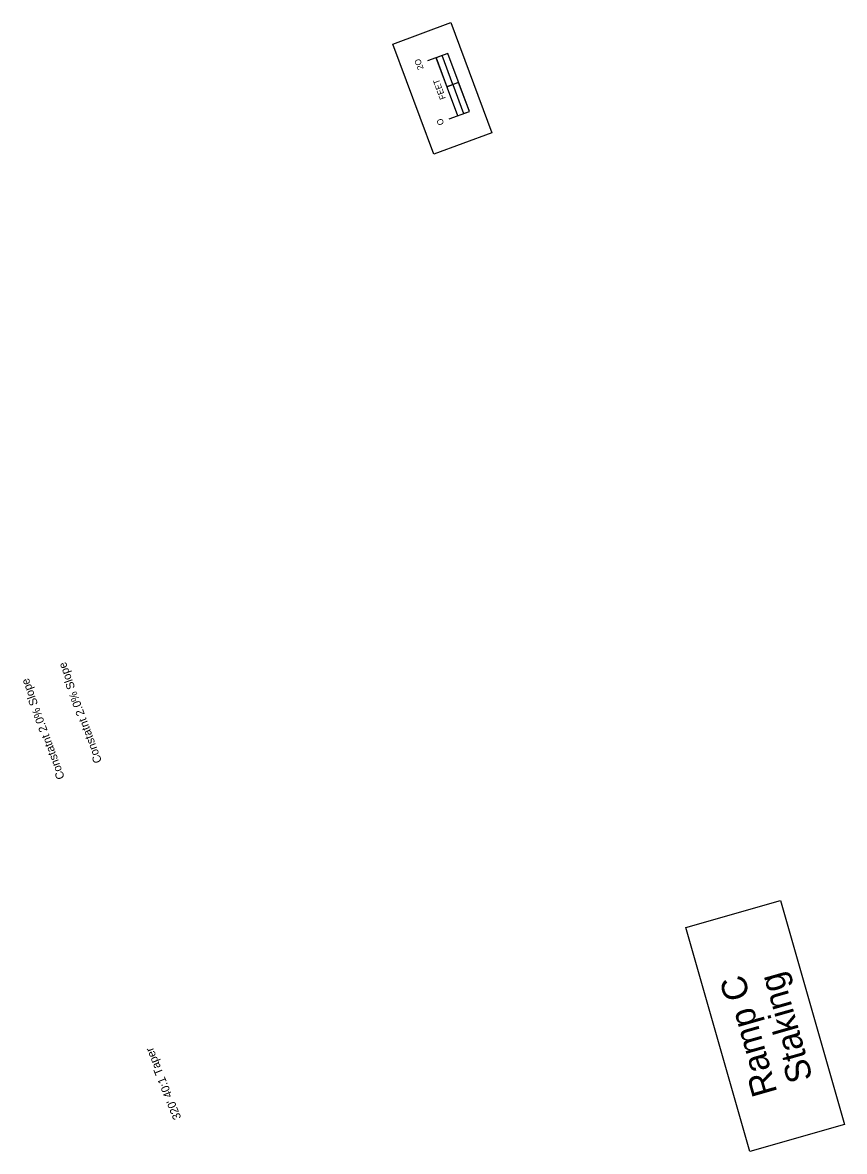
# Model space of a CAD drawing. Extents: x 20506035 to 20507470, y 7969245 to 7972296.
# Drawn here: x 20506341.6 to 20506607.2, y 7970028.9 to 7970394 of the extents above; entities that cross this region are included whole.
import ezdxf

# ---------------------------------------------------------------- set-up
doc = ezdxf.new("R2010")
doc.units = 0
doc.layers.add('_CIVIL_CONSTRUCTION', color=7, linetype='Continuous')
doc.layers.add('dsnStdShading', color=7, linetype='Continuous')

msp = doc.modelspace()

# ---------------------------------------------------------------- linework, layer by layer
at = {"layer": '_CIVIL_CONSTRUCTION'}
msp.add_line((20506482.55, 7970374.65), (20506478.8, 7970373.26), dxfattribs=at)
msp.add_line((20506482.55, 7970374.65), (20506478.8, 7970373.26), dxfattribs=at)
for points in [[(20506474.54, 7970351.41), (20506461.32, 7970387.04), (20506480.07, 7970393.99), (20506493.29, 7970358.37)], [(20506474.54, 7970351.41), (20506461.32, 7970387.04), (20506480.07, 7970393.99), (20506493.29, 7970358.37)], [(20506480.66, 7970373.95), (20506477.19, 7970383.32), (20506475.32, 7970382.63), (20506478.8, 7970373.26)], [(20506486.03, 7970365.27), (20506482.55, 7970374.65), (20506480.66, 7970373.95), (20506484.14, 7970364.57)]]:
    msp.add_lwpolyline(points, close=True, dxfattribs=at)
for points in [[(20506479.47, 7970362.84), (20506486.03, 7970365.27), (20506479.07, 7970384.02), (20506472.51, 7970381.59)], [(20506482.28, 7970363.88), (20506475.32, 7970382.63)]]:
    msp.add_lwpolyline(points, dxfattribs=at)
at = {"layer": 'dsnStdShading'}
for points in [[(20506586.63, 7970110.06), (20506607.23, 7970037.62), (20506576.64, 7970028.92), (20506556.04, 7970101.36)], [(20506576.64, 7970028.92), (20506556.04, 7970101.36), (20506586.63, 7970110.06), (20506607.23, 7970037.62)]]:
    msp.add_lwpolyline(points, close=True, dxfattribs=at)

# ---------------------------------------------------------------- texts
at = {"layer": '_CIVIL_CONSTRUCTION'}
for s, height, rotation, p in [('2O', 2, 110.3566, (20506471.29, 7970379.14)), ('FEET', 2, 110.3566, (20506478.48, 7970369.53)), ('O', 2, 110.3566, (20506477.93, 7970361.22)), ('Constatnt 2.0% Slope', 2.664, 109.9481, (20506367.32, 7970155.04)), ('Constatnt 2.0% Slope', 2.664, 109.9481, (20506355.31, 7970149.78)), ("320' 40:1 Taper", 2.664, 111.9665, (20506392.97, 7970039.81))]:
    msp.add_text(s, height=height, rotation=rotation, dxfattribs=at).set_placement(p)
at = {"layer": 'dsnStdShading'}
for s, p in [('Ramp C', (20506585.61, 7970048.05)), ('Staking', (20506597.08, 7970052.49))]:
    msp.add_text(s, height=8.16, rotation=105.8739, dxfattribs=at).set_placement(p)

doc.saveas('drawing.dxf')
